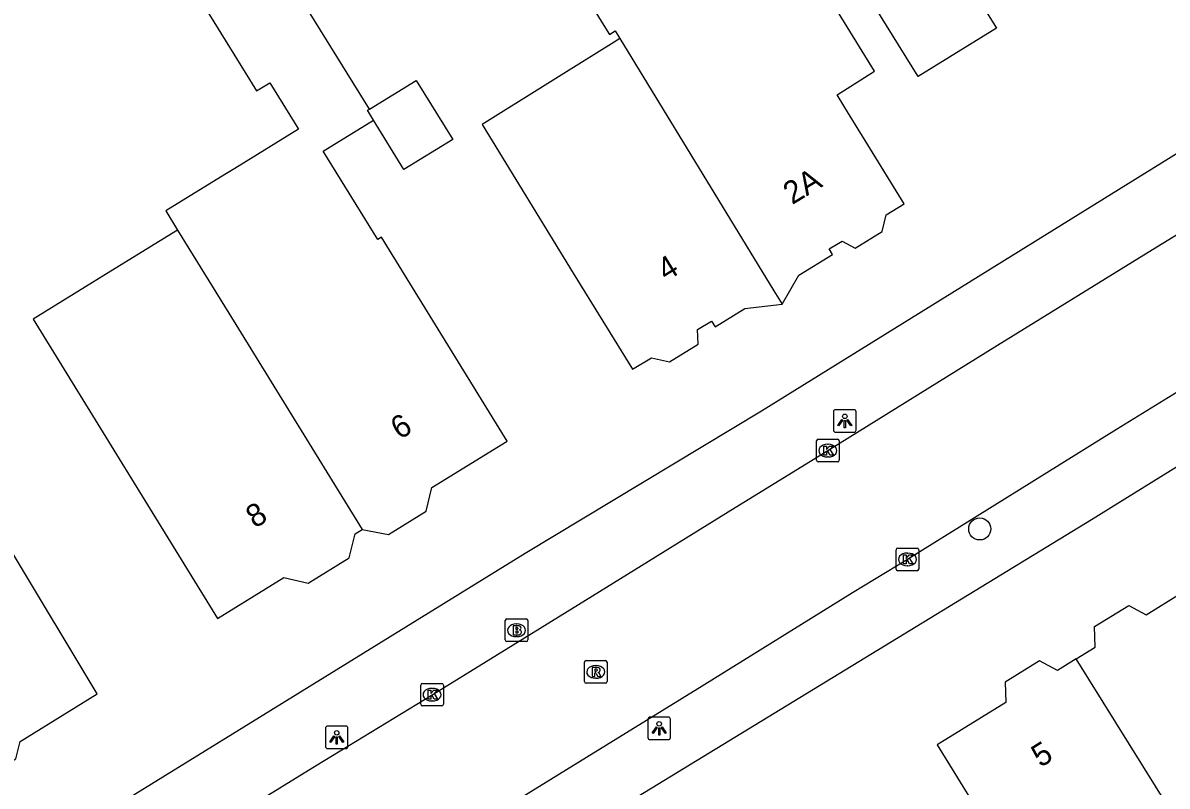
# Model space of a CAD drawing. Extents: x 161354 to 161876, y 382161 to 382804.
# Drawn here: x 161545.7 to 161596.3, y 382355.7 to 382389.5 of the extents above; entities that cross this region are included whole.
import ezdxf

# ---------------------------------------------------------------- set-up
doc = ezdxf.new("R2010")
doc.units = 0
for name, color, linetype in [('IMGEO_Boom', 7, 'Continuous'), ('IMGEO_Brandkraan', 7, 'Continuous'), ('IMGEO_Kolk', 7, 'Continuous'), ('IMGEO_Lichtpunt', 7, 'Continuous'), ('IMGEO_Pand', 7, 'Continuous'), ('IMGEO_Pand_nummerreeks', 7, 'Continuous'), ('IMGEO_Rijbaan_lokaal_open', 7, 'Continuous'), ('IMGEO_Rioolput', 7, 'Continuous'), ('IMGEO_Voetpad_open', 7, 'Continuous')]:
    doc.layers.add(name, color=color, linetype=linetype)

msp = doc.modelspace()

# ---------------------------------------------------------------- linework, layer by layer
at = {"layer": 'IMGEO_Boom'}
msp.add_circle((161588.036, 382367.068), 0.489, dxfattribs=at)
at = {"layer": 'IMGEO_Brandkraan'}
for p, q in [((161567.047, 382362.157), (161567.047, 382363.009)), ((161567.122, 382363.083), (161567.974, 382363.083)), ((161568.048, 382363.009), (161568.048, 382362.157)), ((161567.535, 382362.863), (161567.56, 382362.863)), ((161567.974, 382362.083), (161567.122, 382362.083)), ((161567.558, 382362.303), (161567.533, 382362.303))]:
    msp.add_line(p, q, dxfattribs=at)
for points in [[(161567.047, 382362.157), (161567.047, 382363.009)], [(161567.122, 382363.083), (161567.974, 382363.083)], [(161568.048, 382363.009), (161568.048, 382362.157)], [(161567.395, 382362.783), (161567.395, 382362.383), (161567.608, 382362.383)], [(161567.626, 382362.783), (161567.395, 382362.783)], [(161567.574, 382362.702), (161567.52, 382362.702), (161567.52, 382362.626)], [(161567.52, 382362.626), (161567.573, 382362.626)], [(161567.582, 382362.55), (161567.52, 382362.55), (161567.52, 382362.469)], [(161567.52, 382362.469), (161567.582, 382362.469)], [(161567.974, 382362.083), (161567.122, 382362.083)]]:
    msp.add_lwpolyline(points, dxfattribs=at)
for centre, radius, start, end in [((161567.124, 382363.007), 0.0765, 91.552, 178.448), ((161567.124, 382363.007), 0.0765, 91.552, 178.448), ((161567.972, 382363.007), 0.0765, 1.552, 88.448), ((161567.972, 382363.007), 0.0765, 1.552, 88.448), ((161567.575, 382362.664), 0.0379, 267.8285, 90.9355), ((161567.583, 382362.509), 0.0404, 269.8759, 90.5077), ((161567.63, 382362.638), 0.145, 59.4692, 91.5367), ((161567.655, 382362.685), 0.0922, 285.5137, 58.1501), ((161567.66, 382362.493), 0.105, 301.3115, 78.989), ((161567.124, 382362.159), 0.0765, 181.552, 268.448), ((161567.124, 382362.159), 0.0765, 181.552, 268.448), ((161567.614, 382362.634), 0.251, 268.6676, 293.5347), ((161567.972, 382362.159), 0.0765, 271.552, 358.448), ((161567.972, 382362.159), 0.0765, 271.552, 358.448)]:
    msp.add_arc(centre, radius, start, end, dxfattribs=at)
for centre, major_axis, ratio, start_param, end_param in [((161567.534, 382362.583), (-0.387, 0.002), 0.722429, 4.712389, 7.853982), ((161567.559, 382362.583), (-0.39, 0.002), 0.717154, 1.570796, 4.712389)]:
    msp.add_ellipse(centre, major_axis=major_axis, ratio=ratio, start_param=start_param, end_param=end_param, dxfattribs=at)
at = {"layer": 'IMGEO_Kolk'}
for p, q in [((161580.815, 382370.107), (161580.815, 382370.959)), ((161580.89, 382371.033), (161581.742, 382371.033)), ((161581.303, 382370.813), (161581.328, 382370.813)), ((161581.816, 382370.959), (161581.816, 382370.107)), ((161581.742, 382370.033), (161580.89, 382370.033)), ((161581.326, 382370.253), (161581.301, 382370.253)), ((161584.336, 382365.291), (161584.336, 382366.143)), ((161584.411, 382366.217), (161585.263, 382366.217)), ((161584.824, 382365.997), (161584.849, 382365.997)), ((161585.337, 382366.143), (161585.337, 382365.291)), ((161585.263, 382365.217), (161584.411, 382365.217)), ((161584.847, 382365.437), (161584.822, 382365.437)), ((161563.311, 382359.308), (161563.311, 382360.16)), ((161563.386, 382360.234), (161564.238, 382360.234)), ((161563.799, 382360.014), (161563.824, 382360.014)), ((161564.312, 382360.16), (161564.312, 382359.308)), ((161563.822, 382359.454), (161563.797, 382359.454)), ((161564.238, 382359.234), (161563.386, 382359.234))]:
    msp.add_line(p, q, dxfattribs=at)
for points in [[(161580.815, 382370.107), (161580.815, 382370.959)], [(161580.89, 382371.033), (161581.742, 382371.033)], [(161581.136, 382370.733), (161581.259, 382370.733), (161581.259, 382370.582), (161581.389, 382370.733), (161581.553, 382370.733), (161581.407, 382370.582), (161581.56, 382370.333), (161581.408, 382370.333), (161581.323, 382370.497), (161581.259, 382370.43), (161581.259, 382370.333), (161581.136, 382370.333), (161581.136, 382370.733)], [(161581.816, 382370.959), (161581.816, 382370.107)], [(161581.742, 382370.033), (161580.89, 382370.033)], [(161584.336, 382365.291), (161584.336, 382366.143)], [(161584.411, 382366.217), (161585.263, 382366.217)], [(161585.337, 382366.143), (161585.337, 382365.291)], [(161584.657, 382365.917), (161584.78, 382365.917), (161584.78, 382365.766), (161584.91, 382365.917), (161585.074, 382365.917), (161584.928, 382365.766), (161585.081, 382365.517), (161584.929, 382365.517), (161584.844, 382365.681), (161584.78, 382365.614), (161584.78, 382365.517), (161584.657, 382365.517), (161584.657, 382365.917)], [(161585.263, 382365.217), (161584.411, 382365.217)], [(161563.311, 382359.308), (161563.311, 382360.16)], [(161563.386, 382360.234), (161564.238, 382360.234)], [(161563.632, 382359.934), (161563.755, 382359.934), (161563.755, 382359.783), (161563.885, 382359.934), (161564.049, 382359.934), (161563.903, 382359.783), (161564.056, 382359.534), (161563.904, 382359.534), (161563.819, 382359.698), (161563.755, 382359.631), (161563.755, 382359.534), (161563.632, 382359.534), (161563.632, 382359.934)], [(161564.312, 382360.16), (161564.312, 382359.308)], [(161564.238, 382359.234), (161563.386, 382359.234)]]:
    msp.add_lwpolyline(points, dxfattribs=at)
for centre, start, end in [((161580.892, 382370.957), 91.552, 178.448), ((161580.892, 382370.957), 91.552, 178.448), ((161581.74, 382370.957), 1.552, 88.448), ((161581.74, 382370.957), 1.552, 88.448), ((161580.892, 382370.109), 181.552, 268.448), ((161580.892, 382370.109), 181.552, 268.448), ((161581.74, 382370.109), 271.552, 358.448), ((161581.74, 382370.109), 271.552, 358.448), ((161584.413, 382366.141), 91.552, 178.448), ((161584.413, 382366.141), 91.552, 178.448), ((161585.261, 382366.141), 1.552, 88.448), ((161585.261, 382366.141), 1.552, 88.448), ((161584.413, 382365.293), 181.552, 268.448), ((161584.413, 382365.293), 181.552, 268.448), ((161585.261, 382365.293), 271.552, 358.448), ((161585.261, 382365.293), 271.552, 358.448), ((161563.388, 382360.158), 91.552, 178.448), ((161563.388, 382360.158), 91.552, 178.448), ((161564.236, 382360.158), 1.552, 88.448), ((161564.236, 382360.158), 1.552, 88.448), ((161563.388, 382359.31), 181.552, 268.448), ((161563.388, 382359.31), 181.552, 268.448), ((161564.236, 382359.31), 271.552, 358.448), ((161564.236, 382359.31), 271.552, 358.448)]:
    msp.add_arc(centre, 0.0765, start, end, dxfattribs=at)
for centre, major_axis, ratio, start_param, end_param in [((161581.302, 382370.533), (-0.387, 0.002), 0.722429, 4.712389, 7.853982), ((161581.327, 382370.533), (-0.39, 0.002), 0.717154, 1.570796, 4.712389), ((161584.823, 382365.717), (-0.387, 0.002), 0.722429, 4.712389, 7.853982), ((161584.848, 382365.717), (-0.39, 0.002), 0.717154, 1.570796, 4.712389), ((161563.798, 382359.734), (-0.387, 0.002), 0.722429, 4.712389, 7.853982), ((161563.823, 382359.734), (-0.39, 0.002), 0.717154, 1.570796, 4.712389)]:
    msp.add_ellipse(centre, major_axis=major_axis, ratio=ratio, start_param=start_param, end_param=end_param, dxfattribs=at)
at = {"layer": 'IMGEO_Lichtpunt'}
for p, q in [((161581.566, 382372.248), (161581.566, 382371.441)), ((161581.566, 382372.248), (161581.566, 382371.441)), ((161582.468, 382372.343), (161581.66, 382372.343)), ((161582.468, 382372.343), (161581.66, 382372.343)), ((161582.562, 382371.441), (161582.562, 382372.248)), ((161582.562, 382371.441), (161582.562, 382372.248)), ((161581.66, 382371.347), (161582.468, 382371.347)), ((161581.66, 382371.347), (161582.468, 382371.347)), ((161573.358, 382358.645), (161573.358, 382357.838)), ((161573.358, 382358.645), (161573.358, 382357.838)), ((161574.26, 382358.74), (161573.452, 382358.74)), ((161574.26, 382358.74), (161573.452, 382358.74)), ((161574.354, 382357.838), (161574.354, 382358.645)), ((161574.354, 382357.838), (161574.354, 382358.645)), ((161559.097, 382358.25), (161559.097, 382357.443)), ((161559.097, 382358.25), (161559.097, 382357.443)), ((161559.999, 382358.345), (161559.191, 382358.345)), ((161559.999, 382358.345), (161559.191, 382358.345)), ((161560.093, 382357.443), (161560.093, 382358.25)), ((161560.093, 382357.443), (161560.093, 382358.25)), ((161573.452, 382357.744), (161574.26, 382357.744)), ((161573.452, 382357.744), (161574.26, 382357.744)), ((161559.191, 382357.349), (161559.999, 382357.349)), ((161559.191, 382357.349), (161559.999, 382357.349))]:
    msp.add_line(p, q, dxfattribs=at)
for points in [[(161581.94, 382371.912), (161581.979, 382371.884), (161581.791, 382371.622), (161581.753, 382371.649), (161581.94, 382371.912)], [(161582.042, 382371.864), (161582.089, 382371.864), (161582.089, 382371.542), (161582.042, 382371.542), (161582.042, 382371.864)], [(161582.152, 382371.884), (161582.19, 382371.911), (161582.377, 382371.649), (161582.338, 382371.621), (161582.152, 382371.884)], [(161559.471, 382357.914), (161559.51, 382357.886), (161559.322, 382357.624), (161559.284, 382357.651), (161559.471, 382357.914)], [(161559.683, 382357.886), (161559.721, 382357.913), (161559.908, 382357.651), (161559.869, 382357.623), (161559.683, 382357.886)], [(161573.732, 382358.309), (161573.771, 382358.281), (161573.583, 382358.019), (161573.545, 382358.046), (161573.732, 382358.309)], [(161573.834, 382358.261), (161573.881, 382358.261), (161573.881, 382357.939), (161573.834, 382357.939), (161573.834, 382358.261)], [(161573.944, 382358.281), (161573.982, 382358.308), (161574.169, 382358.046), (161574.13, 382358.018), (161573.944, 382358.281)], [(161559.573, 382357.866), (161559.62, 382357.866), (161559.62, 382357.544), (161559.573, 382357.544), (161559.573, 382357.866)]]:
    msp.add_lwpolyline(points, dxfattribs=at)
for centre in [(161582.065, 382372.046), (161573.857, 382358.443), (161559.596, 382358.048)]:
    msp.add_circle(centre, 0.0994, dxfattribs=at)
for centre, start, end in [((161581.66, 382372.248), 90, 180), ((161581.66, 382372.248), 90, 180), ((161582.468, 382372.248), 0, 90), ((161582.468, 382372.248), 0, 90), ((161581.66, 382371.441), 180, 270), ((161581.66, 382371.441), 180, 270), ((161582.468, 382371.441), 270, 0), ((161582.468, 382371.441), 270, 360), ((161573.452, 382358.645), 90, 180), ((161573.452, 382358.645), 90, 180), ((161574.26, 382358.645), 0, 90), ((161574.26, 382358.645), 0, 90), ((161559.191, 382358.25), 90, 180), ((161559.191, 382358.25), 90, 180), ((161559.999, 382358.25), 0, 90), ((161559.999, 382358.25), 0, 90), ((161559.191, 382357.443), 180, 270), ((161559.191, 382357.443), 180, 270), ((161559.999, 382357.443), 270, 0), ((161559.999, 382357.443), 270, 360), ((161573.452, 382357.838), 180, 270), ((161573.452, 382357.838), 180, 270), ((161574.26, 382357.838), 270, 0), ((161574.26, 382357.838), 270, 360)]:
    msp.add_arc(centre, 0.0946, start, end, dxfattribs=at)
at = {"layer": 'IMGEO_Pand'}
for points in [[(161579.293, 382377.012), (161580.036, 382378.292), (161581.525, 382379.209), (161581.374, 382379.454), (161581.943, 382379.804), (161582.517, 382379.494), (161583.717, 382380.233), (161583.89, 382380.962), (161584.693, 382381.456), (161582.071, 382385.714), (161581.726, 382386.275), (161583.383, 382387.315), (161578.668, 382394.995), (161573.347, 382391.715), (161572.575, 382392.973), (161570.117, 382391.468), (161571.41, 382389.345), (161571.654, 382388.945), (161571.916, 382389.106), (161572.123, 382388.767)], [(161581.645, 382393.017), (161585.108, 382395.155), (161587.292, 382391.62), (161588.771, 382389.226), (161585.309, 382387.087), (161581.645, 382393.017)], [(161561.043, 382385.642), (161556.705, 382392.638), (161554.275, 382391.141), (161553.46, 382390.639), (161556.043, 382386.446), (161556.634, 382386.81), (161557.903, 382384.749), (161555.082, 382383.012), (161554.643, 382382.742), (161552.034, 382381.136), (161552.559, 382380.284)], [(161572.123, 382388.767), (161571.863, 382388.605), (161569.633, 382387.215), (161568.809, 382386.701), (161566.021, 382384.963), (161570.058, 382378.39), (161572.68, 382374.132), (161573.512, 382374.644), (161574.306, 382374.455), (161575.575, 382375.237), (161575.557, 382375.888), (161576.169, 382376.265), (161576.327, 382376.008), (161577.649, 382376.822), (161579.293, 382377.012)], [(161572.123, 382388.767), (161578.926, 382377.608), (161579.293, 382377.012)], [(161561.043, 382385.642), (161563.11, 382386.913), (161564.723, 382384.29), (161562.568, 382382.965), (161561.221, 382385.156)], [(161561.221, 382385.156), (161560.955, 382385.588), (161561.043, 382385.642)], [(161560.716, 382367.043), (161561.888, 382366.823), (161563.556, 382367.85), (161563.808, 382368.906), (161567.129, 382370.951), (161561.571, 382379.977), (161561.406, 382379.875), (161558.997, 382383.786), (161561.221, 382385.156)], [(161552.559, 382380.284), (161549.798, 382378.584), (161546.166, 382376.347), (161554.319, 382363.106), (161557.257, 382364.915), (161558.326, 382364.66), (161560.151, 382365.784), (161560.405, 382366.852), (161560.716, 382367.043)], [(161552.559, 382380.284), (161555.13, 382376.11), (161560.716, 382367.043)], [(161542.751, 382355.974), (161543.409, 382356.379), (161544.243, 382356.181), (161545.408, 382356.898), (161545.591, 382357.669), (161548.998, 382359.767), (161541.411, 382372.389), (161543.83, 382373.843), (161542.804, 382375.51)], [(161592.301, 382361.316), (161593.136, 382361.832), (161593.108, 382362.748), (161594.62, 382363.681), (161595.388, 382363.268), (161598.437, 382365.151), (161600.014, 382362.599), (161600.346, 382362.804), (161602.448, 382359.401), (161605.123, 382361.05), (161605.705, 382360.108)], [(161592.301, 382361.316), (161591.468, 382360.801), (161590.682, 382361.224), (161589.163, 382360.285), (161589.189, 382359.389), (161586.148, 382357.51), (161587.708, 382354.984), (161587.387, 382354.786), (161589.477, 382351.404), (161589.821, 382351.617), (161592.716, 382346.933), (161589.951, 382345.224)], [(161599.308, 382350.054), (161592.301, 382361.316)]]:
    msp.add_lwpolyline(points, dxfattribs=at)
at = {"layer": 'IMGEO_Rijbaan_lokaal_open'}
for points in [[(161552.51, 382352.791), (161558.736, 382356.63), (161563.81, 382359.731), (161570.286, 382363.724), (161577.21, 382368.009), (161581.313, 382370.53), (161588.821, 382375.192), (161595.489, 382379.316), (161598.349, 382381.063), (161606.195, 382385.906)], [(161609.313, 382380.856), (161601.422, 382375.975), (161597.335, 382373.472), (161594.082, 382371.461), (161584.84, 382365.72), (161582.402, 382364.234), (161575.759, 382360.113), (161563.07, 382352.279), (161557.478, 382348.912), (161555.662, 382347.771)]]:
    msp.add_lwpolyline(points, dxfattribs=at)
at = {"layer": 'IMGEO_Rioolput'}
for p, q in [((161570.551, 382360.316), (161570.551, 382361.168)), ((161570.626, 382361.242), (161571.478, 382361.242)), ((161571.039, 382361.022), (161571.064, 382361.022)), ((161571.552, 382361.168), (161571.552, 382360.316)), ((161571.062, 382360.462), (161571.037, 382360.462)), ((161571.478, 382360.242), (161570.626, 382360.242))]:
    msp.add_line(p, q, dxfattribs=at)
for points in [[(161570.551, 382360.316), (161570.551, 382361.168)], [(161570.626, 382361.242), (161571.478, 382361.242)], [(161571.14, 382360.94), (161570.888, 382360.942), (161570.888, 382360.542)], [(161571.552, 382361.168), (161571.552, 382360.316)], [(161570.888, 382360.542), (161571.012, 382360.542), (161571.012, 382360.704), (161571.023, 382360.704)], [(161571.066, 382360.861), (161571.012, 382360.861), (161571.012, 382360.78)], [(161571.012, 382360.78), (161571.064, 382360.78)], [(161571.07, 382360.675), (161571.141, 382360.542), (161571.281, 382360.542), (161571.216, 382360.668)], [(161571.478, 382360.242), (161570.626, 382360.242)]]:
    msp.add_lwpolyline(points, dxfattribs=at)
for centre, radius, start, end in [((161570.628, 382361.166), 0.0765, 91.552, 178.448), ((161570.628, 382361.166), 0.0765, 91.552, 178.448), ((161571.139, 382360.83), 0.109, 350.3612, 89.416), ((161571.476, 382361.166), 0.0765, 1.552, 88.448), ((161571.476, 382361.166), 0.0765, 1.552, 88.448), ((161571.022, 382360.651), 0.0533, 26.0293, 88.6989), ((161571.048, 382360.969), 0.19, 274.7715, 282.9687), ((161571.072, 382360.765), 0.0964, 77.0061, 93.1865), ((161571.086, 382360.822), 0.0378, 276.6634, 79.6772), ((161571.137, 382360.83), 0.112, 277.5842, 350.9817), ((161571.121, 382360.615), 0.108, 29.5134, 73.7905), ((161570.628, 382360.318), 0.0765, 181.552, 268.448), ((161570.628, 382360.318), 0.0765, 181.552, 268.448), ((161571.476, 382360.318), 0.0765, 271.552, 358.448), ((161571.476, 382360.318), 0.0765, 271.552, 358.448)]:
    msp.add_arc(centre, radius, start, end, dxfattribs=at)
for centre, major_axis, ratio, start_param, end_param in [((161571.038, 382360.742), (-0.387, 0.002), 0.722429, 4.712389, 7.853982), ((161571.063, 382360.742), (-0.39, 0.002), 0.717154, 1.570796, 4.712389)]:
    msp.add_ellipse(centre, major_axis=major_axis, ratio=ratio, start_param=start_param, end_param=end_param, dxfattribs=at)
at = {"layer": 'IMGEO_Voetpad_open'}
for points in [[(161617.144, 382396.335), (161578.374, 382372.283), (161567.929, 382365.979), (161532.97, 382344.41), (161519.365, 382335.787), (161506.91, 382326.302), (161500, 382320.746), (161495.67, 382317.265)], [(161622.482, 382385.769), (161592.982, 382367.466), (161570.924, 382353.999), (161525.486, 382325.795), (161515.87, 382318.353), (161502.943, 382308.001)]]:
    msp.add_lwpolyline(points, dxfattribs=at)

# ---------------------------------------------------------------- texts
at = {"layer": 'IMGEO_Pand_nummerreeks'}
for s, rotation, p in [('2A', 31.3179, (161579.737, 382381.391)), ('4', 31.6101, (161574.167, 382378.005)), ('6', 31.484, (161562.376, 382370.995)), ('8', 31.4838, (161555.974, 382367.074)), ('5', 31.8736, (161590.719, 382356.489))]:
    msp.add_text(s, height=1, rotation=rotation, dxfattribs=at).set_placement(p)

doc.saveas('drawing.dxf')
